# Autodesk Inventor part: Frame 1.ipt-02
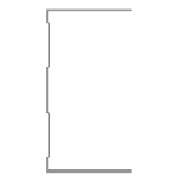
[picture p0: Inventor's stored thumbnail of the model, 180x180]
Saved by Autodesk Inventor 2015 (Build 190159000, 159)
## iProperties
IsCustomPart: 1
Created: 2015-04
Part Number: Frame 1.ipt-02
Material: Aluminum 6061
Description: Kévin Novo
Document SubType Name: Modeling
Standard: Kevin
Designer: suporte
Standards Organization: Kevin
Language: en-US
Size Designation: (Unnamed 2)
Categories: <MemberInstance><Categories><Category DisplayName="Structural Shapes" InternalName="089c4875-fa83-4c05-b084-43b9cc11f5ed" Mnemonic="GRDR"><CategoryParameter Dis
Density: 2.7 g/cm^3
Appearance: Aluminum - Flat
_CCFamilyMember: 2
_CCFamilyDisplayName: Kévin - Kévin Novo
_FrameMemberDoc: Frame Member File
_Version: 15.0.0
_GetPNFromCC: 1
G_W: 50,000 mm
G_H: 75,000 mm
G_L: 2100,000 mm
+4E66BC71-A5B6-4B13-A663-E2628F09967B+CUTDETAIL1: Notch
+B2C040C6-DBC5-486E-99E8-A4085CE8CCBA+CUTDETAIL2: Notch
Author: suporte
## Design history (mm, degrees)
node "Start Plane"
node "End Plane"
sketch "Sketch"
  geometry: L1 (24.7, 37.5)-(24.7, 36.9); L2 (24.7, 36.9)-(-24.7, 36.9); L3 (-24.7, -36.9)-(24.7, -36.9); L4 (24.7, -36.9)-(24.7, -37.5); L5 (24.7, -37.5)-(-25.3, -37.5); L6 (-25.3, 37.5)-(24.7, 37.5); L7 (-24.7, 36.9)-(-24.7, 31.9); L8 (-24.7, 31.9)-(-23.3, 30.5); L9 (-23.3, 30.5)-(-23.3, 10.934); L10 (-23.3, 10.934)-(-24.7, 9.534); L11 (-24.7, 9.534)-(-24.7, -9.534); L12 (-24.7, -9.534)-(-23.3, -10.934); L13 (-23.3, -10.934)-(-23.3, -30.5); L14 (-23.3, -30.5)-(-24.7, -31.9); L15 (-24.7, -31.9)-(-24.7, -36.9); L16 (-25.3, -37.5)-(-25.3, -31.651); L17 (-25.3, -31.651)-(-23.9, -30.251); L18 (-23.9, -30.251)-(-23.9, -11.183); L19 (-23.9, -11.183)-(-25.3, -9.783); L20 (-25.3, -9.783)-(-25.3, 9.783); L21 (-25.3, 9.783)-(-23.9, 11.183); L22 (-23.9, 11.183)-(-23.9, 30.251); L23 (-23.9, 30.251)-(-25.3, 31.651); L24 (-25.3, 31.651)-(-25.3, 37.5); L25 (-25.3, 0)-(30.37, 0); 3 further points
  constraints: 50 end point, 10 point on line, 9 parallel, 5 perpendicular, 4 equal length, 3 midpoint, 3 vertical, 2 vertical alignment, 1 collinear, 1 horizontal, 1 horizontal alignment
  dimensions: "d3" = 0.6 distance of L1.start L1.end (= d6); "d5" = 75 distance between parallel lines of L5 L6; "d6" = 0.6 distance between parallel lines of L24 L7 (= d8); "d7" = 0.6 distance between parallel lines of L8 L23 (= d8); "d8" = 0.6 distance between parallel lines of L22 L9 (= d12); "Espessura" = 0.6 distance between parallel lines of L17 L14; "d10" = 0.6 distance between parallel lines of L13 L18 (= Espessura); "d11" = 0.6 distance between parallel lines of L12 L19 (= Espessura); "d12" = 0.6 distance between parallel lines of L21 L10 (= d11); "d13" = 5 distance of L2.end L7.end; "d15" = 135 deg angle of L9 L8; "d16" = 2 distance between parallel lines of L24 L9; "d17" = 50 distance of L6.start L1.start
extrude "Body" join sketch "Sketch" stored distance "d24" = 0.13; taper "d25" = 0 deg
node "Driven Length"
  sketch "Sketch10"
    geometry: L1 (0, 0)-(10, 0) reference
    constraints: 2 end point, 1 horizontal
  workplane "Work Plane7"
  sketch "Sketch11"
    geometry: L1 (-2, 0)-(12, 0) reference; L2 (-2, 2100)-(12, 2100) reference
    dimensions: "d27" = 2100 distance between parallel lines of L1 L2 (derived)
workplane "Work Plane8"
workplane "Work Plane9"
workplane "Work Plane10"
sketch "Sketch12"
  geometry: L1 (24.7, 37.5)-(24.7, 36.9); L2 (24.7, 36.9)-(-24.7, 36.9); L3 (-24.7, 36.9)-(-24.7, 31.9); L4 (-24.7, 31.9)-(-23.3, 30.5); L5 (-23.3, 30.5)-(-23.3, 10.934); L6 (-23.3, 10.934)-(-24.7, 9.534); L7 (-24.7, 9.534)-(-24.7, -9.534); L8 (-24.7, -9.534)-(-23.3, -10.934); L9 (-23.3, -10.934)-(-23.3, -30.5); L10 (-23.3, -30.5)-(-24.7, -31.9); L11 (-24.7, -31.9)-(-24.7, -36.9); L12 (-24.7, -36.9)-(24.7, -36.9); L13 (24.7, -36.9)-(24.7, -37.5); L14 (24.7, -37.5)-(-25.3, -37.5); L15 (-25.3, -37.5)-(-25.3, -31.651); L16 (-25.3, -31.651)-(-23.9, -30.251); L17 (-23.9, -30.251)-(-23.9, -11.183); L18 (-23.9, -11.183)-(-25.3, -9.783); L19 (-25.3, -9.783)-(-25.3, 9.783); L20 (-25.3, 9.783)-(-23.9, 11.183); L21 (-23.9, 11.183)-(-23.9, 30.251); L22 (-23.9, 30.251)-(-25.3, 31.651); L23 (-25.3, 31.651)-(-25.3, 37.5); L24 (-25.3, 37.5)-(24.7, 37.5)
  constraints: 48 end point, 10 point on line
extrude "Extrusion3" cut sketch "Sketch12" stored distance "d36" = 0.13; taper "d37" = 0 deg
workplane "Work Plane11"
workplane "Work Plane12"
workplane "Work Plane13"
sketch "Sketch13"
  geometry: L1 (24.7, 37.5)-(24.7, 36.9); L2 (24.7, 36.9)-(-24.7, 36.9); L3 (-24.7, 36.9)-(-24.7, 31.9); L4 (-24.7, 31.9)-(-23.3, 30.5); L5 (-23.3, 30.5)-(-23.3, 10.934); L6 (-23.3, 10.934)-(-24.7, 9.534); L7 (-24.7, 9.534)-(-24.7, -9.534); L8 (-24.7, -9.534)-(-23.3, -10.934); L9 (-23.3, -10.934)-(-23.3, -30.5); L10 (-23.3, -30.5)-(-24.7, -31.9); L11 (-24.7, -31.9)-(-24.7, -36.9); L12 (-24.7, -36.9)-(24.7, -36.9); L13 (24.7, -36.9)-(24.7, -37.5); L14 (24.7, -37.5)-(-25.3, -37.5); L15 (-25.3, -37.5)-(-25.3, -31.651); L16 (-25.3, -31.651)-(-23.9, -30.251); L17 (-23.9, -30.251)-(-23.9, -11.183); L18 (-23.9, -11.183)-(-25.3, -9.783); L19 (-25.3, -9.783)-(-25.3, 9.783); L20 (-25.3, 9.783)-(-23.9, 11.183); L21 (-23.9, 11.183)-(-23.9, 30.251); L22 (-23.9, 30.251)-(-25.3, 31.651); L23 (-25.3, 31.651)-(-25.3, 37.5); L24 (-25.3, 37.5)-(24.7, 37.5)
  constraints: 48 end point, 10 point on line
extrude "Extrusion4" cut sketch "Sketch13" stored distance "d38" = 0.13; taper "d39" = 0 deg
body "Solid1"
other parameters: "G_OFFSET_START" = 0 [user parameter; used in 1 equation term], "G_OFFSET_END" = 0 [user parameter; used in 1 equation term], "d22" = 0 (computed from G_OFFSET_START), "G_L" = 2100 (= d27) [user parameter], "d34" = 90 deg
